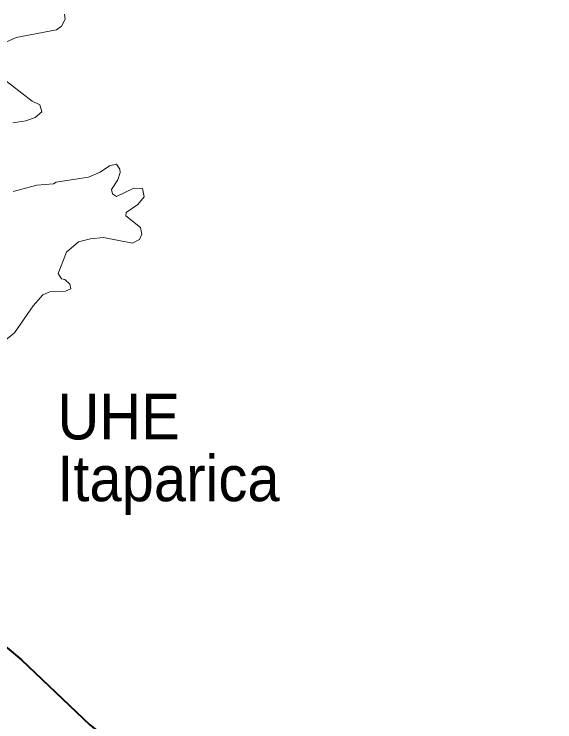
# Model space of a CAD drawing. Extents: x -1643653 to 4543381, y 1624270 to 13878484.
# Drawn here: x 578592 to 584514, y 8987135 to 8994882 of the extents above; entities that cross this region are included whole.
import ezdxf
from ezdxf.enums import TextEntityAlignment as Align

# ---------------------------------------------------------------- set-up
doc = ezdxf.new("R2010")
doc.units = 0
doc.header["$LTSCALE"] = 200
for name, color, linetype, lineweight in [('12', 7, 'Continuous', 25), ('25', 7, 'Continuous', 13), ('60', 7, 'Continuous', 13)]:
    doc.layers.add(name, color=color, linetype=linetype, lineweight=lineweight)
doc.layers.add('42', color=7, linetype='Continuous')

msp = doc.modelspace()

# ---------------------------------------------------------------- linework, layer by layer
at = {"layer": '12', "lineweight": 40}
msp.add_lwpolyline([(577759.9, 8988875.8), (577832.5, 8988674.7), (577901.5, 8988571.1), (578184.7, 8988310.3), (578513.4, 8987946.2), (578671.2, 8987814.3), (579419.2, 8987100.9), (579808.1, 8986794.1), (580283, 8986357.3), (580496.3, 8986108), (581364.8, 8985224.5), (581561.3, 8985062.5), (582162.5, 8984452.7), (582384.7, 8984161.9), (582616.4, 8983918.8), (582880.2, 8983596.7), (583472.4, 8982628.4), (583582.5, 8982317.7), (583621.7, 8982083.2), (583591.6, 8981897.8), (583552.5, 8981370), (583461.7, 8980518.1), (583461.7, 8980001.2)], dxfattribs=at)
at = {"layer": '25'}
for points in [[(578461.3, 8994556.7), (578615, 8994628.2), (579056.6, 8994710.7), (579110.2, 8994751.7), (579148.9, 8994826.5), (579144.5, 8994883.2)], [(578461.3, 8994556.7), (578615, 8994628.2), (579056.6, 8994710.7), (579110.2, 8994751.7), (579148.9, 8994826.5), (579144.5, 8994883.2)], [(578578, 8993693.5), (578718.8, 8993716), (578822.5, 8993752.7), (578893.8, 8993811.3), (578874.4, 8993888.2), (578790.1, 8993930), (578451.3, 8994193.1)], [(578578, 8993693.5), (578718.8, 8993716), (578822.5, 8993752.7), (578893.8, 8993811.3), (578874.4, 8993888.2), (578790.1, 8993930), (578451.3, 8994193.1)], [(578446.9, 8991274.5), (578595.4, 8991394.1), (578801.1, 8991690.5), (578904.7, 8991809.2), (578982.8, 8991841.6), (579155.2, 8991848.1), (579213.7, 8991874.2), (579201.1, 8991927.8), (579146.8, 8991975.6), (579112.1, 8991984.6), (579075.6, 8992042.7), (579166.3, 8992278.3), (579295.8, 8992388.4), (579427.6, 8992423.1), (579570.5, 8992438.3), (579888.8, 8992373.7), (579965.9, 8992414.4), (579989.8, 8992474.5), (579975.3, 8992547.4), (579813.6, 8992672.6), (579818.5, 8992711.8), (579946.6, 8992799.3), (580015.8, 8992883.9), (579996.4, 8992972), (579903.2, 8992976.5), (579711.6, 8992886), (579670, 8992916.1), (579657.1, 8992961.4), (579728.3, 8993069.6), (579752, 8993147.2), (579747.7, 8993186.3), (579714.6, 8993238.2), (579635.4, 8993223), (579533.5, 8993151.6), (579406, 8993097.6), (579053.2, 8993043), (579021.4, 8993026.3), (578840, 8993009.1), (578582.4, 8992940.3)], [(578446.9, 8991274.5), (578595.4, 8991394.1), (578801.1, 8991690.5), (578904.7, 8991809.2), (578982.8, 8991841.6), (579155.2, 8991848.1), (579213.7, 8991874.2), (579201.1, 8991927.8), (579146.8, 8991975.6), (579112.1, 8991984.6), (579075.6, 8992042.7), (579166.3, 8992278.3), (579295.8, 8992388.4), (579427.6, 8992423.1), (579570.5, 8992438.3), (579888.8, 8992373.7), (579965.9, 8992414.4), (579989.8, 8992474.5), (579975.3, 8992547.4), (579813.6, 8992672.6), (579818.5, 8992711.8), (579946.6, 8992799.3), (580015.8, 8992883.9), (579996.4, 8992972), (579903.2, 8992976.5), (579711.6, 8992886), (579670, 8992916.1), (579657.1, 8992961.4), (579728.3, 8993069.6), (579752, 8993147.2), (579747.7, 8993186.3), (579714.6, 8993238.2), (579635.4, 8993223), (579533.5, 8993151.6), (579406, 8993097.6), (579053.2, 8993043), (579021.4, 8993026.3), (578840, 8993009.1), (578582.4, 8992940.3)]]:
    msp.add_lwpolyline(points, dxfattribs=at)
at = {"layer": '60', "lineweight": 25}
msp.add_spline([(814781, 9009175.5), (814787.2, 9009173.4), (814796.9, 9009173.4), (814799.4, 9009172.4), (814805.1, 9009174.5), (814805.6, 9009176.5), (814811.7, 9009179.5), (814811.7, 9009179.5), (814801.5, 9009181), (814790.7, 9009181.5), (814784.1, 9009183.1), (814777.4, 9009185.1), (814778.4, 9009175.5)], degree=3, dxfattribs=at)

# ---------------------------------------------------------------- texts
at = {"layer": '42', "width": 0.95}
for s, p in [('UHE', (579736.7, 8990226.1)), ('Itaparica', (580281.3, 8989550))]:
    msp.add_text(s, height=500, dxfattribs=at).set_placement(p, align=Align.CENTER)

doc.saveas('drawing.dxf')
